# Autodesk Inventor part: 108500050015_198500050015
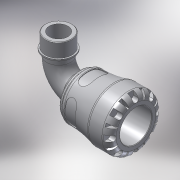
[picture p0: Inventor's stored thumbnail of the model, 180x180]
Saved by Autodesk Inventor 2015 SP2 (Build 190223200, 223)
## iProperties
Created: 2016-12
Part Number: 108500050015_198500050015
Material: PVC-Piping
Description: PLASSON 90° ELBOW WITH THREADED MALE OFFTAKE 50X1.1/2" SERIES 1
Document SubType Name: Modeling
Designer: KIM
Mass: 440.359 g
Surface Area: 664.383 cm^2
Volume: 314.542 cm^3
Density: 1.4 g/cm^3
Appearance: Smooth - White
Author: KIM
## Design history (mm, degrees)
derived "1085.ipt"
feature "Solid1::1085.ipt"
tag "TaggingFeature1"
body "Solid1"
other parameters: "d1" = 33.18, "d3" = 62.5, "d4" = 85, "d8" = 72.25, "d13" = 9, "d14" = 9, "d15" = 0, "d17" = 360 deg, "d19" = 8 deg, "d20" = 1, "d21" = 1, "d22" = 8 deg, "d24" = 0, "d26" = 360 deg, "d33" = 8.5, "d43" = 66.3, "d51" = 0.85, "d54" = 17.5, "d55" = 11, "d57" = 17.64, "d58" = 0, "d74" = 0, "d78" = 79, "d82" = 1, "d115" = 360 deg, "d207" = 90 deg, "d228" = 14.875, "d247" = 1.7, "d248" = 4.74, "d268" = 39.7375, "d269" = 4.74, "d270" = 122, "d276" = 47.803, "d277" = 21, "d278" = 52.5833, "d279" = 68, "d280" = 23.1, "d281" = 7.17045, "d283" = 43.0227, "d286" = 0, "d287" = 0, "d288" = 33.4621, "d290" = 11.63865, "d292" = 30 deg, "E_" = 85, "l_" = 79, "A_" = 122, "A_1" = 68, "l_2" = 21, "R_" = 47.803, "d9" = 11.25, "d11" = 85, "d12" = 62.5, "d289" = 33.4621
